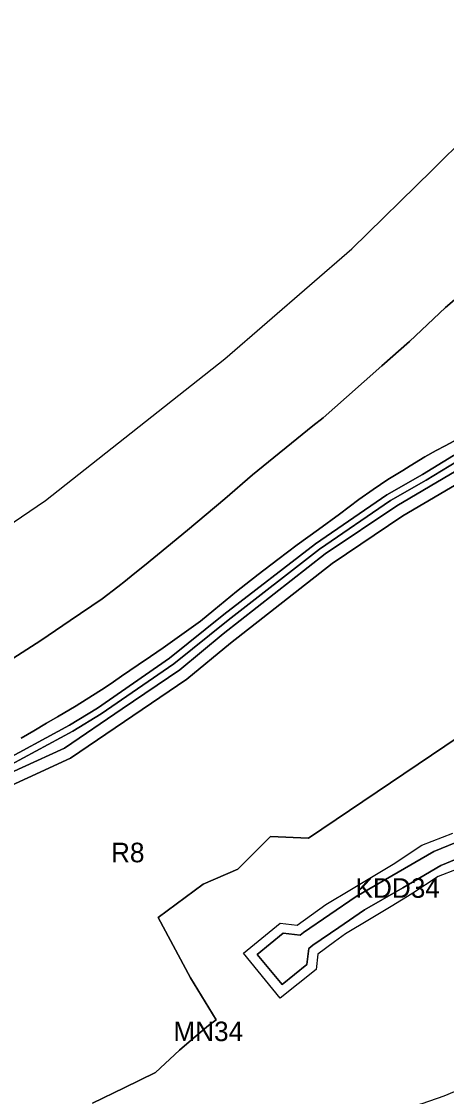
# Model space of a CAD drawing. Extents: x 7428841 to 7433518, y 5545054 to 5546840.
# Drawn here: x 7431352 to 7431569, y 5546005 to 5546555 of the extents above; entities that cross this region are included whole.
import ezdxf

# ---------------------------------------------------------------- set-up
doc = ezdxf.new("R2010")
doc.units = 0
for name, color, linetype in [('linie_rozgraniczajace', 7, 'Continuous'), ('linie_zabudowy_nieprzekraczalne', 7, 'Continuous'), ('oznaczenia_przeznaczen', 7, 'Continuous')]:
    doc.layers.add(name, color=color, linetype=linetype)

msp = doc.modelspace()

# ---------------------------------------------------------------- linework, layer by layer
at = {"layer": 'linie_rozgraniczajace'}
for points in [[(7431294.78, 5546263.35), (7431363.88, 5546310.19), (7431455.51, 5546382.62), (7431520.49, 5546439.04), (7431561.48, 5546479.2), (7431579.86, 5546497.22), (7431670.62, 5546559.16)], [(7431347.16, 5546229.41), (7431361.51, 5546238.67), (7431376.42, 5546248.84), (7431392.78, 5546259.94), (7431400.76, 5546266.13), (7431404.74, 5546269.22), (7431408.73, 5546272.32), (7431414.45, 5546277.02), (7431425.88, 5546286.43), (7431436.4, 5546295.09), (7431455.53, 5546311.07), (7431469.65, 5546323.43), (7431500.61, 5546348.39), (7431505.77, 5546352.56), (7431517.75, 5546363.12), (7431535.86, 5546379.1), (7431549.99, 5546391.56), (7431568.37, 5546408.98), (7431592.58, 5546429.54)], [(7431592.58, 5546429.54), (7431568.37, 5546408.98), (7431549.99, 5546391.56), (7431535.86, 5546379.1), (7431517.75, 5546363.12), (7431505.77, 5546352.56), (7431500.61, 5546348.39), (7431469.65, 5546323.43), (7431455.53, 5546311.07), (7431436.4, 5546295.09), (7431425.88, 5546286.43), (7431414.45, 5546277.02), (7431408.73, 5546272.32), (7431404.74, 5546269.22), (7431400.76, 5546266.13), (7431392.78, 5546259.94), (7431376.42, 5546248.84), (7431361.51, 5546238.67), (7431347.16, 5546229.41)], [(7431338.24, 5546174.92), (7431376.11, 5546195.36), (7431390.44, 5546204), (7431427.33, 5546229.51), (7431455.1, 5546251.84), (7431501.9, 5546288.09), (7431538.36, 5546313.12), (7431556.69, 5546323.61), (7431572.45, 5546333.17), (7431616.06, 5546355.16), (7431662.33, 5546373.92), (7431701.56, 5546386.93), (7431709.83, 5546390.41), (7431719.21, 5546390.93), (7431756.14, 5546396.71), (7431780.54, 5546399.55), (7431803.57, 5546400.9), (7431847.87, 5546401.12), (7431909.37, 5546399.02)], [(7431909.37, 5546399.02), (7431920.42, 5546398.14), (7431920.37, 5546397.33), (7431920.2, 5546394.64), (7431909.17, 5546395.53), (7431847.82, 5546397.62), (7431803.68, 5546397.41), (7431780.84, 5546396.06), (7431756.62, 5546393.25), (7431719.58, 5546387.45), (7431710.63, 5546386.95), (7431702.79, 5546383.65), (7431698.44, 5546382.21), (7431663.54, 5546370.63), (7431617.51, 5546351.97), (7431574.15, 5546330.11), (7431558.47, 5546320.6), (7431540.22, 5546310.15), (7431503.96, 5546285.26), (7431457.27, 5546249.09), (7431429.43, 5546226.71), (7431392.34, 5546201.05), (7431377.84, 5546192.32), (7431339.83, 5546171.8)], [(7431709.83, 5546390.41), (7431701.56, 5546386.93), (7431662.33, 5546373.92), (7431616.06, 5546355.16), (7431572.45, 5546333.17), (7431556.69, 5546323.61), (7431538.36, 5546313.12), (7431501.9, 5546288.09), (7431455.1, 5546251.84), (7431427.33, 5546229.51), (7431390.44, 5546204), (7431376.11, 5546195.36), (7431338.24, 5546174.92)], [(7431576.66, 5546342.76), (7431568.28, 5546338.24), (7431563.62, 5546335.88), (7431557.73, 5546332.54), (7431550.34, 5546327.99), (7431546.52, 5546325.61), (7431538.81, 5546320.9), (7431531.45, 5546315.84), (7431524.1, 5546310.79), (7431514.22, 5546303.2), (7431503.37, 5546295.4), (7431492.53, 5546287.59), (7431482.58, 5546280.02), (7431472.64, 5546272.45), (7431466.36, 5546267.48), (7431461.56, 5546263.65), (7431449.9, 5546254.16), (7431443.04, 5546248.49), (7431433.49, 5546241.65), (7431428.71, 5546238.22), (7431423.93, 5546234.8), (7431417.59, 5546230.5), (7431411.24, 5546226.2), (7431407, 5546223.3), (7431402.76, 5546220.39), (7431398.55, 5546217.47), (7431394.34, 5546214.55), (7431379.56, 5546205.25), (7431370, 5546199.54), (7431364.38, 5546196.26), (7431357.92, 5546192.45), (7431351.46, 5546188.65)], [(7431351.46, 5546188.65), (7431357.92, 5546192.45), (7431364.38, 5546196.26), (7431370, 5546199.54), (7431379.56, 5546205.25), (7431394.34, 5546214.55), (7431398.55, 5546217.47), (7431402.76, 5546220.39), (7431407, 5546223.3), (7431411.24, 5546226.2), (7431417.59, 5546230.5), (7431423.93, 5546234.8), (7431428.71, 5546238.22), (7431433.49, 5546241.65), (7431443.04, 5546248.49), (7431449.9, 5546254.16), (7431461.56, 5546263.65), (7431466.36, 5546267.48), (7431472.64, 5546272.45), (7431482.58, 5546280.02), (7431492.53, 5546287.59), (7431503.37, 5546295.4), (7431514.22, 5546303.2), (7431524.1, 5546310.79), (7431531.45, 5546315.84), (7431538.81, 5546320.9), (7431546.52, 5546325.61), (7431550.34, 5546327.99), (7431557.73, 5546332.54), (7431563.62, 5546335.88), (7431568.28, 5546338.24), (7431576.66, 5546342.76)], [(7431339.83, 5546171.8), (7431377.84, 5546192.32), (7431392.34, 5546201.05), (7431429.43, 5546226.71), (7431457.27, 5546249.09), (7431503.96, 5546285.26), (7431540.22, 5546310.15), (7431558.47, 5546320.6), (7431574.15, 5546330.11)], [(7431573.88, 5546325.35), (7431543.41, 5546307.44), (7431506.81, 5546282.87), (7431480.76, 5546262.43), (7431454.71, 5546242), (7431432.53, 5546223.62), (7431403.08, 5546203.62), (7431373.63, 5546183.63), (7431351.94, 5546173.68), (7431330.24, 5546163.72)], [(7431330.24, 5546163.72), (7431351.94, 5546173.68), (7431373.63, 5546183.63), (7431403.08, 5546203.62), (7431432.53, 5546223.62), (7431454.71, 5546242), (7431480.76, 5546262.43), (7431506.81, 5546282.87), (7431543.41, 5546307.44), (7431573.88, 5546325.35)], [(7431332.86, 5546158.33), (7431376.59, 5546178.38), (7431436.14, 5546218.81), (7431458.47, 5546237.33), (7431510.34, 5546278.01), (7431546.61, 5546302.36), (7431581.61, 5546322.94)], [(7431581.61, 5546322.94), (7431546.61, 5546302.36), (7431510.34, 5546278.01), (7431458.47, 5546237.33), (7431436.14, 5546218.81), (7431376.59, 5546178.38), (7431332.86, 5546158.33)], [(7431603.1, 5546208.27), (7431498.28, 5546137.46), (7431478.97, 5546138.43), (7431462.11, 5546121.67), (7431444.41, 5546114.05), (7431421.49, 5546096.9), (7431437.99, 5546066.14), (7431451.03, 5546044.59), (7431447.18, 5546041.68), (7431439.76, 5546035.41), (7431432.34, 5546029.14), (7431420.1, 5546017.66), (7431403.99, 5546009.81), (7431387.89, 5546001.96)], [(7431387.89, 5546001.96), (7431403.99, 5546009.81), (7431420.1, 5546017.66), (7431432.34, 5546029.14), (7431439.76, 5546035.41), (7431447.18, 5546041.68), (7431451.03, 5546044.59), (7431437.99, 5546066.14), (7431421.49, 5546096.9), (7431444.41, 5546114.05), (7431462.11, 5546121.67), (7431478.97, 5546138.43), (7431498.28, 5546137.46), (7431603.1, 5546208.27)], [(7431601.44, 5546138.2), (7431565.99, 5546123.45), (7431546.48, 5546112.14), (7431526.97, 5546100.83), (7431513.77, 5546091.81), (7431500.57, 5546082.79), (7431498.42, 5546081.08), (7431497.43, 5546072.94), (7431484.84, 5546062.59), (7431472.15, 5546078.05), (7431485.32, 5546088.87), (7431494.09, 5546087.86), (7431495.82, 5546089.23), (7431522.7, 5546107.6), (7431562.44, 5546130.63), (7431580.23, 5546138.04)], [(7431580.23, 5546138.04), (7431562.44, 5546130.63), (7431522.7, 5546107.6), (7431495.82, 5546089.23), (7431494.09, 5546087.86), (7431485.32, 5546088.87), (7431472.15, 5546078.05), (7431484.84, 5546062.59), (7431497.43, 5546072.94), (7431498.42, 5546081.08), (7431500.57, 5546082.79), (7431513.77, 5546091.81), (7431526.97, 5546100.83), (7431546.48, 5546112.14), (7431565.99, 5546123.45), (7431601.44, 5546138.2)]]:
    msp.add_lwpolyline(points, dxfattribs=at)
at = {"layer": 'linie_zabudowy_nieprzekraczalne'}
for points in [[(7431574.29, 5546121.64), (7431564.58, 5546117.89), (7431551.19, 5546109.04), (7431540.61, 5546102.62), (7431529.53, 5546095.96), (7431517.19, 5546088.55), (7431511.67, 5546084.46), (7431503.13, 5546078.19), (7431502.16, 5546070.34), (7431483.92, 5546055.6), (7431465.11, 5546078.74), (7431483.79, 5546094.08), (7431492.6, 5546093.06), (7431507.19, 5546103.53), (7431520.28, 5546111.43), (7431541.58, 5546124.27), (7431556.27, 5546133.97), (7431572.08, 5546140.12)], [(7431179.86, 5545828.51), (7431194.55, 5545832.95), (7431208.56, 5545838.51), (7431222.38, 5545847.36), (7431241, 5545860.79), (7431254.18, 5545867.16), (7431290.1, 5545877.07), (7431303.51, 5545880.27), (7431315.58, 5545884.55), (7431328.71, 5545890.98), (7431356.1, 5545909.93), (7431377.12, 5545923.45), (7431455.24, 5545969.15), (7431477.61, 5545979.11), (7431507.9, 5545987.31), (7431541.37, 5545997.7), (7431556.39, 5546001.76), (7431567.62, 5546005.71), (7431576.19, 5546009.27), (7431579.49, 5546011.06)]]:
    msp.add_lwpolyline(points, dxfattribs=at)

# ---------------------------------------------------------------- texts
at = {"layer": 'oznaczenia_przeznaczen'}
for s, p in [('R8', (7431397.36, 5546125.17)), ('KDD34', (7431522.39, 5546107.02)), ('MN34', (7431429.24, 5546033.69))]:
    msp.add_text(s, height=10, dxfattribs=at).set_placement(p)

doc.saveas('drawing.dxf')
